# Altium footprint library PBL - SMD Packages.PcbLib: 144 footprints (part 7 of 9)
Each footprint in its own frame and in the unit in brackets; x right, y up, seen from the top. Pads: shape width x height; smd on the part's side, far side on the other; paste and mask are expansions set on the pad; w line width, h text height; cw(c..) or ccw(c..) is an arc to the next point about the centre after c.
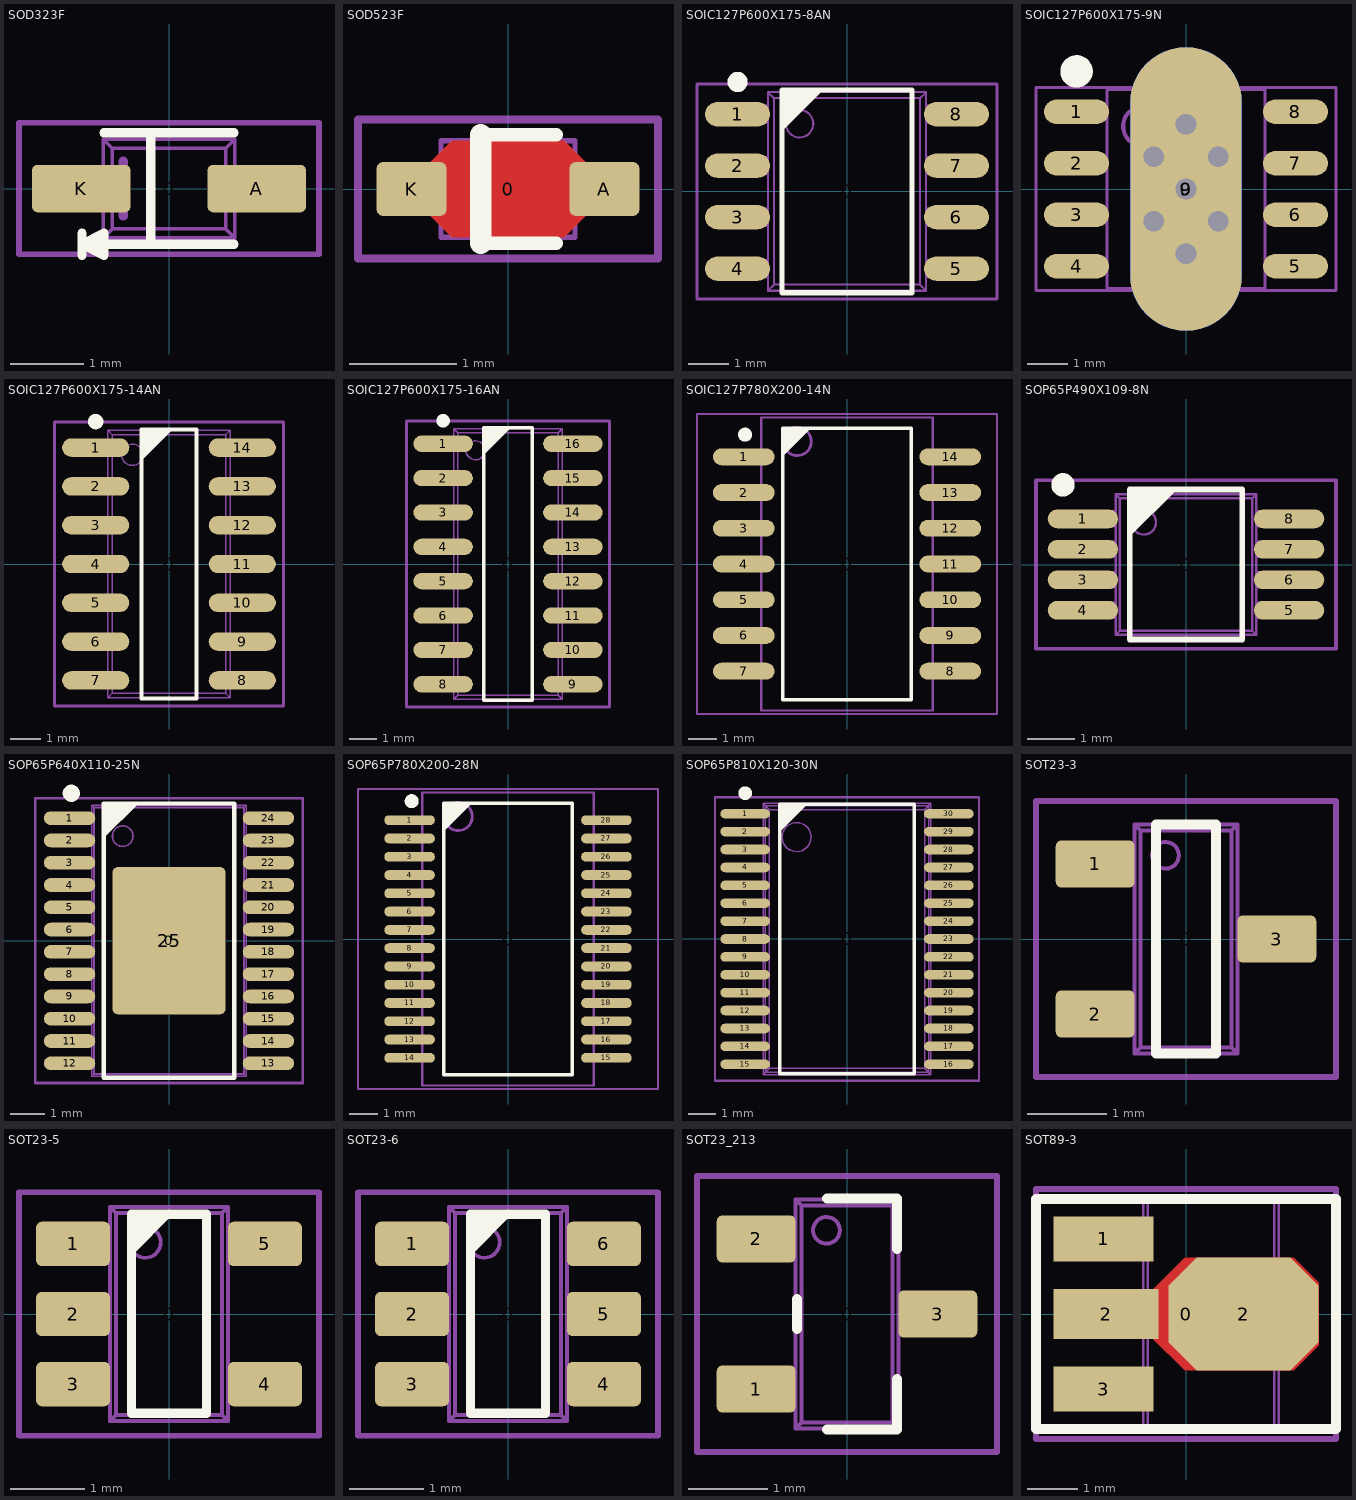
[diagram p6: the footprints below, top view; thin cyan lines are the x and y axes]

## SOD323F [mm] "SOD-323; 2 Leads; Body 2.7 x 1.6 mm, (LxW)"
height 1.35
pads (3):
  round 0.508 on Mech15: 0(0,0)
  rrect25% 1.35x0.65 smd: A(1.2,0) K(-1.2,0)
Top Overlay:
  lines w0.127: -1.189,-0.912 -1.189,-0.612 ; -0.889,0.762 0.889,0.762 ; -0.25,-0.762 -0.25,0.762 ; 0.889,-0.762 -0.889,-0.762 -1.189,-0.762 ; -1.189,-0.762 -0.889,-0.612 -0.889,-0.912 -1.189,-0.762
13 - 3D Top Side:
  lines w0.05: -0.9,-0.2 -1.25,-0.2 -1.25,0.2 -0.9,0.2 ; 0.9,-0.2 1.25,-0.2 1.25,0.2 0.9,0.2 ; -0.9,-0.675 0.9,-0.675 ; -0.9,-0.675 -0.9,0.675 ; -0.9,-0.675 -0.776,-0.551 ; -0.9,0.675 0.9,0.675 ; -0.9,0.675 -0.776,0.551 ; -0.776,-0.551 0.776,-0.551 ; -0.776,-0.551 -0.776,0.551 ; -0.776,0.551 0.776,0.551 ; 0.776,-0.551 0.9,-0.675 ; 0.776,-0.551 0.776,0.551 ; 0.776,0.551 0.9,0.675 ; 0.9,-0.675 0.9,0.675
  lines w0.127: -0.625,-0.375 -0.625,0.375
15 - Top Courtyards:
  lines w0.076: -2.05,-0.9 -2.05,0.9 2.05,0.9 2.05,-0.9 -2.05,-0.9
3D body "SOD323F.STEP": height 1, standoff 0, extent -1.25,-0.675 1.25,0.675

## SOD523F [mm] "SOD-523F; 2 Leads; Body 1.3 x 0.9 mm, (LxW)"
height 0.7
pads (3):
  round 0.508 on Mech15: 0(0,0)
  rrect20% 0.65x0.5 smd: A(0.9,0) K(-0.9,0)
Top Layer:
  pour cut-out: -0.725,-0.25 -0.725,0.25 -0.525,0.45 0.525,0.45 0.725,0.25 0.725,-0.25 0.525,-0.45 -0.525,-0.45
Top Overlay:
  lines w0.127: -0.254,-0.508 0.45,-0.508 ; -0.254,0.508 0.45,0.508
  lines w0.2: -0.254,-0.508 -0.254,0.508
  text "." at -0.9,-0.625 h0.05
13 - 3D Top Side:
  lines w0.05: -0.625,-0.175 -0.625,0.175 ; -0.625,-0.175 -0.625,-0.45 0.625,-0.45 0.625,-0.175 ; -0.625,-0.175 -0.85,-0.175 -0.85,0.175 -0.625,0.175 ; -0.625,0.175 -0.625,0.45 0.625,0.45 0.625,0.175 ; 0.625,-0.175 0.625,0.175 ; 0.625,-0.175 0.85,-0.175 0.85,0.175 0.625,0.175
  lines w0.127: -0.425,-0.275 -0.425,0.275
15 - Top Courtyards:
  lines w0.076: -1.4,-0.65 1.4,-0.65 1.4,0.65 -1.4,0.65 -1.4,-0.65
3D body "SOD-523F.STEP": height 0.7, standoff 0, extent -0.85,-0.45 0.85,0.45

## SOIC127P600X175-8AN [mm] "SOIC, 8-Leads, Body 4.9x3.9mm, Pitch 1.27mm, IPC Medium Density"
height 1.75
pads (9):
  round 1 on Mech15: 0(0,0)
  oval 1.6x0.6 smd: 1(-2.7,1.905) 2(-2.7,0.635) 3(-2.7,-0.635) 4(-2.7,-1.905) 5(2.7,-1.905) 6(2.7,-0.635) 7(2.7,0.635) 8(2.7,1.905)
Top Overlay:
  circle w0.25: c-2.7,2.7 r0.125
  region: -1.6,2.5 -0.6,2.5 -1.6,1.5
  lines w0.127: -1.6,-2.5 -1.6,2.5 1.6,2.5 1.6,-2.5 -1.6,-2.5
13 - 3D Top Side:
  circle w0.05: c-1.17,1.67 r0.338
  lines w0.05: -2.631,-2.115 -2.631,-1.695 ; -2.631,-0.845 -2.631,-0.425 ; -2.631,0.425 -2.631,0.845 ; -2.631,1.695 -2.631,2.115 ; -2.543,-2.115 -2.543,-1.695 ; -2.543,-0.845 -2.543,-0.425 ; -2.543,0.425 -2.543,0.845 ; -2.543,1.695 -2.543,2.115 ; -2.403,-2.115 -2.403,-1.695 ; -2.403,-0.845 -2.403,-0.425 ; -2.403,0.425 -2.403,0.845 ; -2.403,1.695 -2.403,2.115 ; -2.113,-2.115 -2.113,-1.695 ; -2.113,-0.845 -2.113,-0.425 ; -2.113,0.425 -2.113,0.845 ; -2.113,1.695 -2.113,2.115 ; -1.95,-2.115 -3,-2.115 -3,-1.695 -1.95,-1.695 ; -1.95,-0.845 -3,-0.845 -3,-0.425 -1.95,-0.425 ; -1.95,0.425 -3,0.425 -3,0.845 -1.95,0.845 ; -1.95,1.695 -3,1.695 -3,2.115 -1.95,2.115 ; 1.95,-2.115 3,-2.115 3,-1.695 1.95,-1.695 ; 1.95,-0.845 3,-0.845 3,-0.425 1.95,-0.425 ; 1.95,0.425 3,0.425 3,0.845 1.95,0.845 ; 1.95,1.695 3,1.695 3,2.115 1.95,2.115 ; 2.113,-2.115 2.113,-1.695 ; 2.113,-0.845 2.113,-0.425 ; 2.113,0.425 2.113,0.845 ; 2.113,1.695 2.113,2.115 ; 2.403,-2.115 2.403,-1.695 ; 2.403,-0.845 2.403,-0.425 ; 2.403,0.425 2.403,0.845 ; 2.403,1.695 2.403,2.115 ; 2.543,-2.115 2.543,-1.695 ; 2.543,-0.845 2.543,-0.425 ; 2.543,0.425 2.543,0.845 ; 2.543,1.695 2.543,2.115 ; 2.631,-2.115 2.631,-1.695 ; 2.631,-0.845 2.631,-0.425 ; 2.631,0.425 2.631,0.845 ; 2.631,1.695 2.631,2.115 ; -1.95,-2.45 1.95,-2.45 ; -1.95,-2.45 -1.95,2.45 ; -1.95,-2.45 -1.801,-2.301 ; -1.95,2.45 -1.801,2.301 ; -1.95,2.45 1.95,2.45 ; -1.801,-2.301 1.801,-2.301 ; -1.801,-2.301 -1.801,2.301 ; -1.801,2.301 1.801,2.301 ; 1.801,-2.301 1.95,-2.45 ; 1.801,-2.301 1.801,2.301 ; 1.801,2.301 1.95,2.45 ; 1.95,-2.45 1.95,2.45
15 - Top Courtyards:
  lines w0.076: -3.7,-2.65 -3.7,2.65 3.7,2.65 3.7,-2.65 -3.7,-2.65
3D body "SOIC-8.STEP": height 1.75, standoff 0, extent -3,-2.45 3,2.45

## SOIC127P600X175-9N [mm] "SOIC, 8-Leads with thermal tab, Body 4.9x3.9mm, Pitch 1.27mm, IPC Medium Density"
height 1.75
pads (11):
  round 1 on Mech15: 0(0,0)
  oval 1.6x0.6 smd: 1(-2.7,1.905) 2(-2.7,0.635) 3(-2.7,-0.635) 4(-2.7,-1.905) 5(2.7,-1.905) 6(2.7,-0.635) 7(2.7,0.635) 8(2.7,1.905)
  oval 2.75x7 smd paste-2: 9(0,0)
  oval 2.75x7 smd far side paste-2: 9(0,0)
via 0,0 diameter 1.016 hole 0.508
via -0.8,0.8 diameter 1.016 hole 0.508
via 0.8,0.8 diameter 1.016 hole 0.508
via 0.8,-0.8 diameter 1.016 hole 0.508
via -0.8,-0.8 diameter 1.016 hole 0.508
via 0,1.6 diameter 1.016 hole 0.508
via 0,-1.6 diameter 1.016 hole 0.508
Top Overlay:
  circle w0.4: c-2.7,2.9 r0.2
13 - 3D Top Side:
  circle w0.1: c-1.05,1.55 r0.5
  lines w0.076: -1.95,-2.45 1.95,-2.45 1.95,2.45 -1.95,2.45 -1.95,-2.45
15 - Top Courtyards:
  lines w0.076: -3.7,-2.5 3.7,-2.5 3.7,2.5 -3.7,2.5 -3.7,-2.5
3D body "SOIC-8.STEP": height 1.75, standoff 0, extent -3,-2.45 3,2.45

## SOIC127P600X175-14AN [mm] "SOIC, 1.27mm pitch, 14 pin, Body 8.65x3.90mm"
height 1.75
pads (15):
  round 1 on Mech15: 0(0,0)
  oval 2.2x0.6 smd: 1(-2.4,3.81) 2(-2.4,2.54) 3(-2.4,1.27) 4(-2.4,0) 5(-2.4,-1.27) 6(-2.4,-2.54) 7(-2.4,-3.81) 8(2.4,-3.81) 9(2.4,-2.54) 10(2.4,-1.27) 11(2.4,0) 12(2.4,1.27) 13(2.4,2.54) 14(2.4,3.81)
Top Overlay:
  circle w0.25: c-2.4,4.66 r0.125
  region: -0.9,4.4 0.1,4.4 -0.9,3.4
  lines w0.127: -0.9,-4.4 -0.9,4.4 0.9,4.4 0.9,-4.4 -0.9,-4.4
13 - 3D Top Side:
  circle w0.05: c-1.2,3.575 r0.35
  lines w0.05: -2.631,-4.02 -2.631,-3.6 ; -2.631,-2.75 -2.631,-2.33 ; -2.631,-1.48 -2.631,-1.06 ; -2.631,-0.21 -2.631,0.21 ; -2.631,1.06 -2.631,1.48 ; -2.631,2.33 -2.631,2.75 ; -2.631,3.6 -2.631,4.02 ; -2.543,-4.02 -2.543,-3.6 ; -2.543,-2.75 -2.543,-2.33 ; -2.543,-1.48 -2.543,-1.06 ; -2.543,-0.21 -2.543,0.21 ; -2.543,1.06 -2.543,1.48 ; -2.543,2.33 -2.543,2.75 ; -2.543,3.6 -2.543,4.02 ; -2.403,-4.02 -2.403,-3.6 ; -2.403,-2.75 -2.403,-2.33 ; -2.403,-1.48 -2.403,-1.06 ; -2.403,-0.21 -2.403,0.21 ; -2.403,1.06 -2.403,1.48 ; -2.403,2.33 -2.403,2.75 ; -2.403,3.6 -2.403,4.02 ; -2.113,-4.02 -2.113,-3.6 ; -2.113,-2.75 -2.113,-2.33 ; -2.113,-1.48 -2.113,-1.06 ; -2.113,-0.21 -2.113,0.21 ; -2.113,1.06 -2.113,1.48 ; -2.113,2.33 -2.113,2.75 ; -2.113,3.6 -2.113,4.02 ; -2,-4.02 -3,-4.02 -3,-3.6 -2,-3.6 ; -2,-2.75 -3,-2.75 -3,-2.33 -2,-2.33 ; -2,-1.48 -3,-1.48 -3,-1.06 -2,-1.06 ; -2,-0.21 -3,-0.21 -3,0.21 -2,0.21 ; -2,1.06 -3,1.06 -3,1.48 -2,1.48 ; -2,2.33 -3,2.33 -3,2.75 -2,2.75 ; -2,3.6 -3,3.6 -3,4.02 -2,4.02 ; 2,-4.02 3,-4.02 3,-3.6 2,-3.6 ; 2,-2.75 3,-2.75 3,-2.33 2,-2.33 ; 2,-1.48 3,-1.48 3,-1.06 2,-1.06 ; 2,-0.21 3,-0.21 3,0.21 2,0.21 ; 2,1.06 3,1.06 3,1.48 2,1.48 ; 2,2.33 3,2.33 3,2.75 2,2.75 ; 2,3.6 3,3.6 3,4.02 2,4.02 ; 2.113,-4.02 2.113,-3.6 ; 2.113,-2.75 2.113,-2.33 ; 2.113,-1.48 2.113,-1.06 ; 2.113,-0.21 2.113,0.21 ; 2.113,1.06 2.113,1.48 ; 2.113,2.33 2.113,2.75 ; 2.113,3.6 2.113,4.02 ; 2.403,-4.02 2.403,-3.6 ; 2.403,-2.75 2.403,-2.33 ; 2.403,-1.48 2.403,-1.06 ; 2.403,-0.21 2.403,0.21 ; 2.403,1.06 2.403,1.48 ; 2.403,2.33 2.403,2.75 ; 2.403,3.6 2.403,4.02 ; 2.543,-4.02 2.543,-3.6 ; 2.543,-2.75 2.543,-2.33 ; 2.543,-1.48 2.543,-1.06 ; 2.543,-0.21 2.543,0.21 ; 2.543,1.06 2.543,1.48 ; 2.543,2.33 2.543,2.75 ; 2.543,3.6 2.543,4.02 ; 2.631,-4.02 2.631,-3.6 ; 2.631,-2.75 2.631,-2.33 ; 2.631,-1.48 2.631,-1.06 ; 2.631,-0.21 2.631,0.21 ; 2.631,1.06 2.631,1.48 ; 2.631,2.33 2.631,2.75 ; 2.631,3.6 2.631,4.02 ; -2,-4.375 2,-4.375 ; -2,-4.375 -1.851,-4.226 ; -2,-4.375 -2,4.375 ; -2,4.375 2,4.375 ; -2,4.375 -1.851,4.226 ; -1.851,-4.226 -1.851,4.226 ; -1.851,-4.226 1.851,-4.226 ; -1.851,4.226 1.851,4.226 ; 1.851,-4.226 1.851,4.226 ; 1.851,-4.226 2,-4.375 ; 1.851,4.226 2,4.375 ; 2,-4.375 2,4.375
15 - Top Courtyards:
  lines w0.1: -3.75,-4.65 -3.75,4.65 3.75,4.65 3.75,-4.65 -3.75,-4.65
3D body "SOIC127P600X175-14AN.stp": height 1.75, standoff 0, extent -3.006,-4.325 3.006,4.325

## SOIC127P600X175-16AN [mm] "SOIC, 1.27mm pitch, 16 pin, Body 9.9x3.90mm"
height 1.75
pads (17):
  round 1 on Mech15: 0(0,0)
  oval 2.2x0.6 smd: 1(-2.4,4.445) 2(-2.4,3.175) 3(-2.4,1.905) 4(-2.4,0.635) 5(-2.4,-0.635) 6(-2.4,-1.905) 7(-2.4,-3.175) 8(-2.4,-4.445) 9(2.4,-4.445) 10(2.4,-3.175) 11(2.4,-1.905) 12(2.4,-0.635) 13(2.4,0.635) 14(2.4,1.905) 15(2.4,3.175) 16(2.4,4.445)
Top Overlay:
  circle w0.25: c-2.4,5.295 r0.125
  region: -0.9,5.035 0.1,5.035 -0.9,4.035
  lines w0.127: -0.9,-5.035 -0.9,5.035 0.9,5.035 0.9,-5.035 -0.9,-5.035
13 - 3D Top Side:
  circle w0.05: c-1.2,4.2 r0.35
  lines w0.05: -2.631,-4.655 -2.631,-4.235 ; -2.631,-3.385 -2.631,-2.965 ; -2.631,-2.115 -2.631,-1.695 ; -2.631,-0.845 -2.631,-0.425 ; -2.631,0.425 -2.631,0.845 ; -2.631,1.695 -2.631,2.115 ; -2.631,2.965 -2.631,3.385 ; -2.631,4.235 -2.631,4.655 ; -2.543,-4.655 -2.543,-4.235 ; -2.543,-3.385 -2.543,-2.965 ; -2.543,-2.115 -2.543,-1.695 ; -2.543,-0.845 -2.543,-0.425 ; -2.543,0.425 -2.543,0.845 ; -2.543,1.695 -2.543,2.115 ; -2.543,2.965 -2.543,3.385 ; -2.543,4.235 -2.543,4.655 ; -2.403,-4.655 -2.403,-4.235 ; -2.403,-3.385 -2.403,-2.965 ; -2.403,-2.115 -2.403,-1.695 ; -2.403,-0.845 -2.403,-0.425 ; -2.403,0.425 -2.403,0.845 ; -2.403,1.695 -2.403,2.115 ; -2.403,2.965 -2.403,3.385 ; -2.403,4.235 -2.403,4.655 ; -2.113,-4.655 -2.113,-4.235 ; -2.113,-3.385 -2.113,-2.965 ; -2.113,-2.115 -2.113,-1.695 ; -2.113,-0.845 -2.113,-0.425 ; -2.113,0.425 -2.113,0.845 ; -2.113,1.695 -2.113,2.115 ; -2.113,2.965 -2.113,3.385 ; -2.113,4.235 -2.113,4.655 ; -2,-4.655 -3,-4.655 -3,-4.235 -2,-4.235 ; -2,-3.385 -3,-3.385 -3,-2.965 -2,-2.965 ; -2,-2.115 -3,-2.115 -3,-1.695 -2,-1.695 ; -2,-0.845 -3,-0.845 -3,-0.425 -2,-0.425 ; -2,0.425 -3,0.425 -3,0.845 -2,0.845 ; -2,1.695 -3,1.695 -3,2.115 -2,2.115 ; -2,2.965 -3,2.965 -3,3.385 -2,3.385 ; -2,4.235 -3,4.235 -3,4.655 -2,4.655 ; 2,-4.655 3,-4.655 3,-4.235 2,-4.235 ; 2,-3.385 3,-3.385 3,-2.965 2,-2.965 ; 2,-2.115 3,-2.115 3,-1.695 2,-1.695 ; 2,-0.845 3,-0.845 3,-0.425 2,-0.425 ; 2,0.425 3,0.425 3,0.845 2,0.845 ; 2,1.695 3,1.695 3,2.115 2,2.115 ; 2,2.965 3,2.965 3,3.385 2,3.385 ; 2,4.235 3,4.235 3,4.655 2,4.655 ; 2.113,-4.655 2.113,-4.235 ; 2.113,-3.385 2.113,-2.965 ; 2.113,-2.115 2.113,-1.695 ; 2.113,-0.845 2.113,-0.425 ; 2.113,0.425 2.113,0.845 ; 2.113,1.695 2.113,2.115 ; 2.113,2.965 2.113,3.385 ; 2.113,4.235 2.113,4.655 ; 2.403,-4.655 2.403,-4.235 ; 2.403,-3.385 2.403,-2.965 ; 2.403,-2.115 2.403,-1.695 ; 2.403,-0.845 2.403,-0.425 ; 2.403,0.425 2.403,0.845 ; 2.403,1.695 2.403,2.115 ; 2.403,2.965 2.403,3.385 ; 2.403,4.235 2.403,4.655 ; 2.543,-4.655 2.543,-4.235 ; 2.543,-3.385 2.543,-2.965 ; 2.543,-2.115 2.543,-1.695 ; 2.543,-0.845 2.543,-0.425 ; 2.543,0.425 2.543,0.845 ; 2.543,1.695 2.543,2.115 ; 2.543,2.965 2.543,3.385 ; 2.543,4.235 2.543,4.655 ; 2.631,-4.655 2.631,-4.235 ; 2.631,-3.385 2.631,-2.965 ; 2.631,-2.115 2.631,-1.695 ; 2.631,-0.845 2.631,-0.425 ; 2.631,0.425 2.631,0.845 ; 2.631,1.695 2.631,2.115 ; 2.631,2.965 2.631,3.385 ; 2.631,4.235 2.631,4.655 ; -2,-5 -2,5 ; -2,-5 -1.851,-4.851 ; -2,-5 2,-5 ; -2,5 -1.851,4.851 ; -2,5 2,5 ; -1.851,-4.851 1.851,-4.851 ; -1.851,-4.851 -1.851,4.851 ; -1.851,4.851 1.851,4.851 ; 1.851,-4.851 2,-5 ; 1.851,-4.851 1.851,4.851 ; 1.851,4.851 2,5 ; 2,-5 2,5
15 - Top Courtyards:
  lines w0.1: -3.75,-5.285 -3.75,5.285 3.75,5.285 3.75,-5.285 -3.75,-5.285
3D body "SOIC-16.STEP": height 1.75, standoff 0, extent -3,-5 3,5

## SOIC127P780X200-14N [mm] "SOIC, 14 Leads, Body 10.5x5.3mm, Pitch 1.27mm, IPC Medium Density"
height 2
pads (15):
  round 1 on Mech15: 0(0,0)
  oval 2.2x0.6 smd: 1(-3.67,3.81) 2(-3.67,2.54) 3(-3.67,1.27) 4(-3.67,0) 5(-3.67,-1.27) 6(-3.67,-2.54) 7(-3.67,-3.81) 8(3.67,-3.81) 9(3.67,-2.54) 10(3.67,-1.27) 11(3.67,0) 12(3.67,1.27) 13(3.67,2.54) 14(3.67,3.81)
Top Overlay:
  circle w0.25: c-3.625,4.6 r0.125
  region: -2.286,4.826 -1.286,4.826 -2.286,3.826
  lines w0.127: -2.286,-4.826 -2.286,4.826 2.286,4.826 2.286,-4.826 -2.286,-4.826
13 - 3D Top Side:
  circle w0.1: c-1.77,4.355 r0.5
  lines w0.076: -3.048,-5.207 -3.048,5.207 3.048,5.207 3.048,-5.207 -3.048,-5.207
15 - Top Courtyards:
  lines w0.076: -5.334,-5.334 -5.334,5.334 5.334,5.334 5.334,-5.334 -5.334,-5.334
3D body "SOIC-14.stp": height 2, standoff 0, extent -3.904,-5.25 3.904,5.25

## SOP65P490X109-8N [mm] "SOP, 0.65mm pitch, 8 pin, Body 3.0x3.0x1.09mm LWH, IPC Medium Density"
height 1.09
pads (9):
  round 1 on Mech15: 0(0,0)
  oval 1.5x0.4 smd: 1(-2.2,0.975) 2(-2.2,0.325) 3(-2.2,-0.325) 4(-2.2,-0.975) 5(2.2,-0.975) 6(2.2,-0.325) 7(2.2,0.325) 8(2.2,0.975)
Top Overlay:
  circle w0.25: c-2.625,1.7 r0.125
  region: -1.2,1.6 -0.2,1.6 -1.2,0.6
  lines w0.127: -1.2,-1.6 1.2,-1.6 1.2,1.6 -1.2,1.6 -1.2,-1.6
13 - 3D Top Side:
  circle w0.05: c-0.9,0.9 r0.26
  lines w0.05: -2.162,-1.135 -2.162,-0.815 ; -2.162,-0.485 -2.162,-0.165 ; -2.162,0.165 -2.162,0.485 ; -2.162,0.815 -2.162,1.135 ; -2.074,-1.135 -2.074,-0.815 ; -2.074,-0.485 -2.074,-0.165 ; -2.074,0.165 -2.074,0.485 ; -2.074,0.815 -2.074,1.135 ; -2.019,-1.135 -2.019,-0.815 ; -2.019,-0.485 -2.019,-0.165 ; -2.019,0.165 -2.019,0.485 ; -2.019,0.815 -2.019,1.135 ; -1.749,-1.135 -1.749,-0.815 ; -1.749,-0.485 -1.749,-0.165 ; -1.749,0.165 -1.749,0.485 ; -1.749,0.815 -1.749,1.135 ; -1.5,-1.135 -2.45,-1.135 -2.45,-0.815 -1.5,-0.815 ; -1.5,-0.485 -2.45,-0.485 -2.45,-0.165 -1.5,-0.165 ; -1.5,0.165 -2.45,0.165 -2.45,0.485 -1.5,0.485 ; -1.5,0.815 -2.45,0.815 -2.45,1.135 -1.5,1.135 ; 1.5,-1.135 2.45,-1.135 2.45,-0.815 1.5,-0.815 ; 1.5,-0.485 2.45,-0.485 2.45,-0.165 1.5,-0.165 ; 1.5,0.165 2.45,0.165 2.45,0.485 1.5,0.485 ; 1.5,0.815 2.45,0.815 2.45,1.135 1.5,1.135 ; 1.749,-1.135 1.749,-0.815 ; 1.749,-0.485 1.749,-0.165 ; 1.749,0.165 1.749,0.485 ; 1.749,0.815 1.749,1.135 ; 2.019,-1.135 2.019,-0.815 ; 2.019,-0.485 2.019,-0.165 ; 2.019,0.165 2.019,0.485 ; 2.019,0.815 2.019,1.135 ; 2.074,-1.135 2.074,-0.815 ; 2.074,-0.485 2.074,-0.165 ; 2.074,0.165 2.074,0.485 ; 2.074,0.815 2.074,1.135 ; 2.162,-1.135 2.162,-0.815 ; 2.162,-0.485 2.162,-0.165 ; 2.162,0.165 2.162,0.485 ; 2.162,0.815 2.162,1.135 ; -1.5,-1.5 -1.413,-1.413 ; -1.5,-1.5 -1.5,1.5 ; -1.5,-1.5 1.5,-1.5 ; -1.5,1.5 1.5,1.5 ; -1.5,1.5 -1.413,1.413 ; -1.413,-1.413 -1.413,1.413 ; -1.413,-1.413 1.413,-1.413 ; -1.413,1.413 1.413,1.413 ; 1.413,-1.413 1.413,1.413 ; 1.413,-1.413 1.5,-1.5 ; 1.413,1.413 1.5,1.5 ; 1.5,-1.5 1.5,1.5
15 - Top Courtyards:
  lines w0.076: -3.2,-1.8 3.2,-1.8 3.2,1.8 -3.2,1.8 -3.2,-1.8
3D body "MSOP-8.STEP": height 1.1, standoff 0, extent -2.45,-1.5 2.45,1.5

## SOP65P640X110-25N [mm] "TSSOP, 24-Leads, Body 7.9x4.5mm (max), Pitch 0.65mm, IPC Medium Density; JEDEC MO-153"
height 1.1
pads (26):
  round 0.508 on Mech15 mask+0.127: 0(0,0)
  oval 1.5x0.4 smd mask+0.127: 1(-2.9,3.575) 2(-2.9,2.925) 3(-2.9,2.275) 4(-2.9,1.625) 5(-2.9,0.975) 6(-2.9,0.325) 7(-2.9,-0.325) 8(-2.9,-0.975) 9(-2.9,-1.625) 10(-2.9,-2.275) 11(-2.9,-2.925) 12(-2.9,-3.575) 13(2.9,-3.575) 14(2.9,-2.925) 15(2.9,-2.275) 16(2.9,-1.625) 17(2.9,-0.975) 18(2.9,-0.325) 19(2.9,0.325) 20(2.9,0.975) 21(2.9,1.625) 22(2.9,2.275) 23(2.9,2.925) 24(2.9,3.575)
  rrect10% 3.3x4.3 smd paste-0.7: 25(0,0)
Top Overlay:
  circle w0.25: c-2.85,4.3 r0.125
  region: -1.9,4 -0.9,4 -1.9,3
  lines w0.127: -1.9,-4 1.9,-4 1.9,4 -1.9,4 -1.9,-4
13 - 3D Top Side:
  drawing of 181 lines, arcs and shapes, not listed
15 - Top Courtyards:
  lines w0.076: -3.9,-4.15 3.9,-4.15 3.9,4.15 -3.9,4.15 -3.9,-4.15
3D body "SOP65P640X110-24N.STEP": height 1.2, standoff 0, extent -3.25,-3.95 3.25,3.95

## SOP65P780X200-28N [mm] "SOP, 28 Leads, Body 10.2x5.3mm, Pitch 0.65mm, IPC Medium Density"
height 2
pads (29):
  round 1 on Mech15: 0(0,0)
  oval 1.8x0.35 smd: 1(-3.5,4.225) 2(-3.5,3.575) 3(-3.5,2.925) 4(-3.5,2.275) 5(-3.5,1.625) 6(-3.5,0.975) 7(-3.5,0.325) 8(-3.5,-0.325) 9(-3.5,-0.975) 10(-3.5,-1.625) 11(-3.5,-2.275) 12(-3.5,-2.925) 13(-3.5,-3.575) 14(-3.5,-4.225) 15(3.5,-4.225) 16(3.5,-3.575) 17(3.5,-2.925) 18(3.5,-2.275) 19(3.5,-1.625) 20(3.5,-0.975) 21(3.5,-0.325) 22(3.5,0.325) 23(3.5,0.975) 24(3.5,1.625) 25(3.5,2.275) 26(3.5,2.925) 27(3.5,3.575) 28(3.5,4.225)
Top Overlay:
  circle w0.25: c-3.425,4.9 r0.125
  region: -2.286,4.826 -1.286,4.826 -2.286,3.826
  lines w0.127: -2.286,-4.826 2.286,-4.826 2.286,4.826 -2.286,4.826 -2.286,-4.826
13 - 3D Top Side:
  circle w0.1: c-1.77,4.355 r0.5
  lines w0.076: -3.048,-5.207 3.048,-5.207 3.048,5.207 -3.048,5.207 -3.048,-5.207
15 - Top Courtyards:
  lines w0.076: -5.334,-5.334 5.334,-5.334 5.334,5.334 -5.334,5.334 -5.334,-5.334
3D body "SOP65P780X200-28N.stp": height 1.88, standoff 0, extent -3.903,-5.1 3.903,5.1

## SOP65P810X120-30N [mm] "SOP, 30-Leads, Body 9.8x6.2mm (max), Pitch 0.65mm, IPC Medium Density"
height 1.2
pads (31):
  round 1 on Mech15: 0(0,0)
  oval 1.8x0.35 smd mask+0.152: 1(-3.7,4.55) 2(-3.7,3.9) 3(-3.7,3.25) 4(-3.7,2.6) 5(-3.7,1.95) 6(-3.7,1.3) 7(-3.7,0.65) 8(-3.7,0) 9(-3.7,-0.65) 10(-3.7,-1.3) 11(-3.7,-1.95) 12(-3.7,-2.6) 13(-3.7,-3.25) 14(-3.7,-3.9) 15(-3.7,-4.55) 16(3.7,-4.55) 17(3.7,-3.9) 18(3.7,-3.25) 19(3.7,-2.6) 20(3.7,-1.95) 21(3.7,-1.3) 22(3.7,-0.65) 23(3.7,0) 24(3.7,0.65) 25(3.7,1.3) 26(3.7,1.95) 27(3.7,2.6) 28(3.7,3.25) 29(3.7,3.9) 30(3.7,4.55)
Top Overlay:
  circle w0.25: c-3.7,5.3 r0.125
  region: -2.45,4.9 -1.45,4.9 -2.45,3.9
  lines w0.127: -2.45,-4.9 -2.45,4.9 2.45,4.9 2.45,-4.9 -2.45,-4.9
13 - 3D Top Side:
  drawing of 227 lines, arcs and shapes, not listed
15 - Top Courtyards:
  lines w0.076: -4.8,-5.15 -4.8,5.15 4.8,5.15 4.8,-5.15 -4.8,-5.15
3D body "LSSOP-30.STEP": height 1.3, standoff 0, extent -4.05,-4.925 4.05,4.925

## SOT23-3 [mm] "SOT23, 3 pin"
height 1.003
pads (4):
  round 0.5 on Mech15: 0(0,0)
  rrect25% 1x0.6 smd: 1(-1.15,0.95) 2(-1.15,-0.95) 3(1.15,0)
Top Overlay:
  lines w0.127: -0.381,-1.45 -0.381,1.45 0.381,1.45 0.381,-1.45 -0.381,-1.45
  text "." at -2.125,0.95 h0.1
13 - 3D Top Side:
  circle w0.05: c-0.26,1.06 r0.169
  lines w0.05: -1.19,-1.19 -1.19,-0.71 ; -1.19,0.71 -1.19,1.19 ; -1.099,-1.19 -1.099,-0.71 ; -1.099,0.71 -1.099,1.19 ; -1.074,-1.19 -1.074,-0.71 ; -1.074,0.71 -1.074,1.19 ; -0.825,-1.19 -0.825,-0.71 ; -0.825,0.71 -0.825,1.19 ; -0.65,-1.19 -1.4,-1.19 -1.4,-0.71 -0.65,-0.71 ; -0.65,0.71 -1.4,0.71 -1.4,1.19 -0.65,1.19 ; 0.65,-0.24 1.4,-0.24 1.4,0.24 0.65,0.24 ; 0.825,-0.24 0.825,0.24 ; 1.074,-0.24 1.074,0.24 ; 1.099,-0.24 1.099,0.24 ; 1.19,-0.24 1.19,0.24 ; -0.65,-1.45 0.65,-1.45 ; -0.65,-1.45 -0.65,1.45 ; -0.65,-1.45 -0.576,-1.376 ; -0.65,1.45 -0.576,1.376 ; -0.65,1.45 0.65,1.45 ; -0.576,-1.376 0.576,-1.376 ; -0.576,-1.376 -0.576,1.376 ; -0.576,1.376 0.576,1.376 ; 0.576,-1.376 0.65,-1.45 ; 0.576,-1.376 0.576,1.376 ; 0.576,1.376 0.65,1.45 ; 0.65,-1.45 0.65,1.45
15 - Top Courtyards:
  lines w0.076: -1.9,-1.75 -1.9,1.75 1.9,1.75 1.9,-1.75 -1.9,-1.75
3D body "SOT23-3.STEP": height 1.29, standoff -0.01, extent -1.4,-1.45 1.4,1.45

## SOT23-5 [mm]
height 1.6
pads (6):
  round 0.5 on Mech15: 0(0,0)
  rrect25% 1x0.6 smd: 1(-1.3,0.95) 2(-1.3,0) 3(-1.3,-0.95) 4(1.3,-0.95) 5(1.3,0.95)
Top Overlay:
  region: -0.508,1.353 0.053,1.353 -0.508,0.792
  lines w0.127: -0.508,-1.347 -0.508,1.353 0.508,1.353 0.508,-1.347 -0.508,-1.347
  text "." at -2.275,0.95 h0.1
13 - 3D Top Side:
  circle w0.05: c-0.32,0.97 r0.208
  lines w0.05: -1.191,-1.15 -1.191,-0.75 ; -1.191,-0.2 -1.191,0.2 ; -1.191,0.75 -1.191,1.15 ; -1.1,-1.15 -1.1,-0.75 ; -1.1,-0.2 -1.1,0.2 ; -1.1,0.75 -1.1,1.15 ; -1.094,-1.15 -1.094,-0.75 ; -1.094,-0.2 -1.094,0.2 ; -1.094,0.75 -1.094,1.15 ; -0.844,-1.15 -0.844,-0.75 ; -0.844,-0.2 -0.844,0.2 ; -0.844,0.75 -0.844,1.15 ; -0.8,-1.15 -1.4,-1.15 -1.4,-0.75 -0.8,-0.75 ; -0.8,-0.2 -1.4,-0.2 -1.4,0.2 -0.8,0.2 ; -0.8,0.75 -1.4,0.75 -1.4,1.15 -0.8,1.15 ; 0.8,-1.15 1.4,-1.15 1.4,-0.75 0.8,-0.75 ; 0.8,0.75 1.4,0.75 1.4,1.15 0.8,1.15 ; 0.844,-1.15 0.844,-0.75 ; 0.844,0.75 0.844,1.15 ; 1.094,-1.15 1.094,-0.75 ; 1.094,0.75 1.094,1.15 ; 1.1,-1.15 1.1,-0.75 ; 1.1,0.75 1.1,1.15 ; 1.191,-1.15 1.191,-0.75 ; 1.191,0.75 1.191,1.15 ; -0.8,-1.45 -0.8,1.45 ; -0.8,-1.45 -0.719,-1.369 ; -0.8,-1.45 0.8,-1.45 ; -0.8,1.45 -0.719,1.369 ; -0.8,1.45 0.8,1.45 ; -0.719,-1.369 0.719,-1.369 ; -0.719,-1.369 -0.719,1.369 ; -0.719,1.369 0.719,1.369 ; 0.719,-1.369 0.8,-1.45 ; 0.719,-1.369 0.719,1.369 ; 0.719,1.369 0.8,1.45 ; 0.8,-1.45 0.8,1.45
15 - Top Courtyards:
  lines w0.076: -2.032,-1.651 -2.032,1.651 2.032,1.651 2.032,-1.651 -2.032,-1.651
3D body "SOT23-5.STEP": height 1.44, standoff -0.01, extent -1.4,-1.45 1.4,1.45

## SOT23-6 [mm]
height 1.6
pads (7):
  round 0.5 on Mech15: 0(0,0)
  rrect25% 1x0.6 smd: 1(-1.3,0.95) 2(-1.3,0) 3(-1.3,-0.95) 4(1.3,-0.95) 5(1.3,0) 6(1.3,0.95)
Top Overlay:
  region: -0.508,1.353 0.053,1.353 -0.508,0.792
  lines w0.127: -0.508,-1.347 -0.508,1.353 0.508,1.353 0.508,-1.347 -0.508,-1.347
  text "." at -2.275,0.95 h0.1
13 - 3D Top Side:
  circle w0.05: c-0.32,0.97 r0.208
  lines w0.05: -1.191,-1.15 -1.191,-0.75 ; -1.191,-0.2 -1.191,0.2 ; -1.191,0.75 -1.191,1.15 ; -1.1,-1.15 -1.1,-0.75 ; -1.1,-0.2 -1.1,0.2 ; -1.1,0.75 -1.1,1.15 ; -1.094,-1.15 -1.094,-0.75 ; -1.094,-0.2 -1.094,0.2 ; -1.094,0.75 -1.094,1.15 ; -0.844,-1.15 -0.844,-0.75 ; -0.844,-0.2 -0.844,0.2 ; -0.844,0.75 -0.844,1.15 ; -0.8,-1.15 -1.4,-1.15 -1.4,-0.75 -0.8,-0.75 ; -0.8,-0.2 -1.4,-0.2 -1.4,0.2 -0.8,0.2 ; -0.8,0.75 -1.4,0.75 -1.4,1.15 -0.8,1.15 ; 0.8,-1.15 1.4,-1.15 1.4,-0.75 0.8,-0.75 ; 0.8,-0.2 1.4,-0.2 1.4,0.2 0.8,0.2 ; 0.8,0.75 1.4,0.75 1.4,1.15 0.8,1.15 ; 0.844,-1.15 0.844,-0.75 ; 0.844,-0.2 0.844,0.2 ; 0.844,0.75 0.844,1.15 ; 1.094,-1.15 1.094,-0.75 ; 1.094,-0.2 1.094,0.2 ; 1.094,0.75 1.094,1.15 ; 1.1,-1.15 1.1,-0.75 ; 1.1,-0.2 1.1,0.2 ; 1.1,0.75 1.1,1.15 ; 1.191,-1.15 1.191,-0.75 ; 1.191,-0.2 1.191,0.2 ; 1.191,0.75 1.191,1.15 ; -0.8,-1.45 0.8,-1.45 ; -0.8,-1.45 -0.719,-1.369 ; -0.8,-1.45 -0.8,1.45 ; -0.8,1.45 0.8,1.45 ; -0.8,1.45 -0.719,1.369 ; -0.719,-1.369 -0.719,1.369 ; -0.719,-1.369 0.719,-1.369 ; -0.719,1.369 0.719,1.369 ; 0.719,-1.369 0.719,1.369 ; 0.719,-1.369 0.8,-1.45 ; 0.719,1.369 0.8,1.45 ; 0.8,-1.45 0.8,1.45
15 - Top Courtyards:
  lines w0.076: -2.032,-1.651 -2.032,1.651 2.032,1.651 2.032,-1.651 -2.032,-1.651
3D body "SOT23-6.STEP": height 1.44, standoff -0.01, extent -1.4,-1.45 1.4,1.45

## SOT23_213 [mm]
height 1.003
pads (4):
  round 0.5 on Mech15: 0(0,0)
  rrect25% 1x0.6 smd: 1(-1.15,-0.95) 2(-1.15,0.95) 3(1.15,0)
Top Overlay:
  lines w0.127: -0.635,-0.191 -0.635,0.191 ; -0.254,-1.46 0.635,-1.46 0.635,-0.826 ; -0.254,1.46 0.635,1.46 0.635,0.826
13 - 3D Top Side:
  circle w0.05: c-0.26,1.06 r0.169
  lines w0.05: -1.19,-1.19 -1.19,-0.71 ; -1.19,0.71 -1.19,1.19 ; -1.099,-1.19 -1.099,-0.71 ; -1.099,0.71 -1.099,1.19 ; -1.074,-1.19 -1.074,-0.71 ; -1.074,0.71 -1.074,1.19 ; -0.825,-1.19 -0.825,-0.71 ; -0.825,0.71 -0.825,1.19 ; -0.65,-1.19 -1.4,-1.19 -1.4,-0.71 -0.65,-0.71 ; -0.65,0.71 -1.4,0.71 -1.4,1.19 -0.65,1.19 ; 0.65,-0.24 1.4,-0.24 1.4,0.24 0.65,0.24 ; 0.825,-0.24 0.825,0.24 ; 1.074,-0.24 1.074,0.24 ; 1.099,-0.24 1.099,0.24 ; 1.19,-0.24 1.19,0.24 ; -0.65,-1.45 -0.576,-1.376 ; -0.65,-1.45 -0.65,1.45 ; -0.65,-1.45 0.65,-1.45 ; -0.65,1.45 0.65,1.45 ; -0.65,1.45 -0.576,1.376 ; -0.576,-1.376 -0.576,1.376 ; -0.576,-1.376 0.576,-1.376 ; -0.576,1.376 0.576,1.376 ; 0.576,-1.376 0.576,1.376 ; 0.576,-1.376 0.65,-1.45 ; 0.576,1.376 0.65,1.45 ; 0.65,-1.45 0.65,1.45
15 - Top Courtyards:
  lines w0.076: -1.9,-1.75 -1.9,1.75 1.9,1.75 1.9,-1.75 -1.9,-1.75
3D body "SOT23-3.STEP": height 1.29, standoff -0.01, extent -1.4,-1.45 1.4,1.45

## SOT89-3 [mm] "JEDEC TO-243 option AA / SOT89"
height 1.7
pads (5):
  round 1 on Mech15: 0(0,0)
  rrect1% 2x0.9 smd: 1(-1.65,1.5) 3(-1.65,-1.5)
  rrect1% 2.1x1 smd: 2(-1.6,0)
  oct 3x2.25 smd: 2(1.15,0)
Top Layer:
  region: -0.7,-0.45 -0.025,-1.125 2.15,-1.125 2.65,-0.625 2.65,0.625 2.15,1.125 -0.025,1.125 -0.7,0.45
Top Overlay:
  lines w0.2: -3,-2.3 -3,2.3 3,2.3 3,-2.3 -3,-2.3
13 - 3D Top Side:
  lines w0.05: -0.85,-1.76 -0.85,-2.35 ; -0.85,-1.24 -0.85,-0.3 ; -0.85,0.3 -0.85,1.24 ; -0.85,1.76 -0.85,2.35 ; 1.85,-0.925 1.85,-2.35 ; 1.85,0.925 1.85,2.35 ; -0.85,-2.35 1.85,-2.35 ; -0.85,-2.35 -0.761,-2.261 ; -0.85,2.35 1.85,2.35 ; -0.85,2.35 -0.761,2.261 ; -0.761,-2.261 1.761,-2.261 ; -0.761,-2.261 -0.761,2.261 ; -0.761,2.261 1.761,2.261 ; 1.761,-2.261 1.761,2.261 ; 1.761,-2.261 1.85,-2.35 ; 1.761,2.261 1.85,2.35 ; -2.25,-1.76 -2.25,-1.24 -0.824,-1.24 -0.824,-1.76 -2.25,-1.76 ; -2.25,-0.3 -0.824,-0.3 -0.824,0.3 -2.25,0.3 -2.25,-0.3 ; -2.25,1.24 -2.25,1.76 -0.824,1.76 -0.824,1.24 -2.25,1.24 ; 1.824,-0.925 1.9,-0.925 2.2,-0.625 2.2,0.625 1.9,0.925 1.824,0.925 1.824,-0.925
15 - Top Courtyards:
  lines w0.127: -3,-2.5 -3,2.5 3,2.5 3,-2.5 -3,-2.5
3D body "SOT89-3.STEP": height 1.69, standoff 0, extent -2.25,-2.35 2.2,2.35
